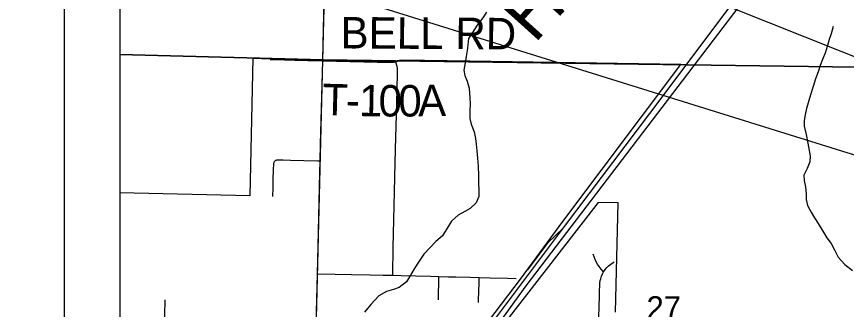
# Model space of a CAD drawing. Extents: x -38.1 to 35.9, y -2.7 to 28.5.
# Drawn here: x 18.424 to 19.92, y 16.626 to 17.155 of the extents above; entities that cross this region are included whole.
import ezdxf

# ---------------------------------------------------------------- set-up
doc = ezdxf.new("R2010")
doc.units = 0
for name, color, linetype in [('GM_X_City_Street', 7, 'Continuous'), ('GM_X_Corporation', 7, 'Continuous'), ('GM_X_Interchange_Ramps', 7, 'Continuous'), ('GM_X_Major_River_Text', 7, 'Continuous'), ('GM_X_Minor_Lake', 7, 'Continuous'), ('GM_X_Minor_River', 7, 'Continuous'), ('GM_X_Section', 7, 'Continuous'), ('GM_X_US_Location', 7, 'Continuous'), ('GM_X_US_Route', 7, 'Continuous'), ('SH_Border', 7, 'Continuous'), ('SH_Data', 7, 'Continuous')]:
    doc.layers.add(name, color=color, linetype=linetype)

msp = doc.modelspace()

# ---------------------------------------------------------------- linework, layer by layer
at = {"layer": 'GM_X_City_Street'}
for points in [[(19.1023, 16.6877), (19.1024, 16.6883), (19.1033, 16.7377), (19.1051, 16.8132), (19.1076, 16.9156), (19.1096, 16.9978), (19.1108, 17.0519), (19.1109, 17.0568), (19.1109, 17.0602), (19.1108, 17.0614), (19.1107, 17.0623), (19.1105, 17.0634), (19.1102, 17.0643), (19.1079, 17.0725), (19.1077, 17.0733)], [(18.8864, 16.8301), (18.8867, 16.8455), (18.8871, 16.8628), (18.8874, 16.8758), (18.8877, 16.8821), (18.8878, 16.8849), (18.8879, 16.8875), (18.888, 16.8889), (18.8882, 16.89), (18.8884, 16.8913), (18.8887, 16.8922), (18.889, 16.8929), (18.8897, 16.8941)], [(18.8897, 16.8941), (18.8903, 16.8946), (18.8908, 16.895), (18.8915, 16.8954), (18.8923, 16.8957), (18.8933, 16.8959), (18.8945, 16.896), (18.8989, 16.896), (18.9047, 16.896), (18.9183, 16.8957), (18.9424, 16.8951), (18.9676, 16.8945), (18.9717, 16.8944)], [(19.4824, 16.6937), (19.4782, 16.699), (19.4746, 16.7034), (19.4715, 16.708), (19.469, 16.7123), (19.4671, 16.7163), (19.4654, 16.721), (19.4638, 16.7257)], [(19.4736, 16.5934), (19.4749, 16.6502), (19.4751, 16.6582), (19.4752, 16.6622), (19.4755, 16.667), (19.4757, 16.6706), (19.476, 16.6743), (19.4766, 16.6783), (19.4773, 16.6814), (19.479, 16.6862), (19.4812, 16.6914), (19.4824, 16.6937), (19.483, 16.6948), (19.4851, 16.698), (19.4882, 16.7018), (19.4914, 16.7047), (19.4958, 16.7081), (19.4996, 16.711), (19.5018, 16.7122)], [(18.9666, 16.6904), (18.9986, 16.6898), (19.0282, 16.6892), (19.0619, 16.6885), (19.0852, 16.688), (19.1023, 16.6877), (19.1174, 16.6872), (19.1704, 16.6859), (19.1858, 16.6856), (19.2031, 16.6852), (19.2162, 16.6849), (19.2422, 16.6843), (19.2583, 16.6839), (19.278, 16.6834), (19.3092, 16.6826), (19.3247, 16.6822)], [(19.1849, 16.6433), (19.1858, 16.6849), (19.1858, 16.6856)], [(19.2571, 16.6386), (19.2573, 16.646), (19.2576, 16.6559), (19.2581, 16.677), (19.2582, 16.6831), (19.2583, 16.6839)], [(18.6838, 16.3345), (18.6838, 16.3354), (18.6842, 16.3477), (18.685, 16.3713), (18.6856, 16.3892), (18.6858, 16.3944), (18.6862, 16.3985), (18.6865, 16.4028), (18.6867, 16.4071), (18.6868, 16.4108), (18.6896, 16.5153), (18.6903, 16.5603), (18.6906, 16.5743), (18.6907, 16.5829), (18.6916, 16.616), (18.6924, 16.6435)]]:
    msp.add_lwpolyline(points, dxfattribs=at)
at = {"layer": 'GM_X_Corporation'}
for points in [[(18.6101, 15.7069), (18.8445, 16.0191), (18.9897, 16.2122), (19.0483, 16.2903), (19.2337, 16.5376), (19.4121, 16.7756), (19.566, 16.98), (19.763, 17.2432), (19.9196, 17.4482), (20.1512, 17.7579), (20.6767, 18.4541), (21.2204, 19.1713), (21.641, 19.7308)], [(18.6101, 15.3282), (18.8021, 15.6262), (18.9395, 15.8264), (19.0058, 15.9302), (19.0089, 15.9495), (19.0142, 16.0977), (19.0173, 16.1531), (19.0191, 16.1912), (19.0199, 16.2263), (19.0305, 16.2532), (19.2347, 16.519), (19.3429, 16.6685), (19.7347, 17.1834), (19.9115, 17.4163)], [(19.3461, 16.6973), (19.3827, 16.7469), (19.4098, 16.7725)]]:
    msp.add_lwpolyline(points, dxfattribs=at)
at = {"layer": 'GM_X_Interchange_Ramps'}
for points in [[(18.9764, 17.0748), (18.9782, 17.1482), (18.98, 17.2128), (18.9809, 17.2588), (18.9815, 17.283), (18.9833, 17.3477), (18.9853, 17.4235), (18.986, 17.4508), (18.9871, 17.4819), (18.9881, 17.5204), (18.9896, 17.5801)], [(18.9683, 16.7664), (18.9683, 16.7674), (18.9712, 16.8726), (18.9717, 16.8944), (18.9724, 16.9242), (18.9764, 17.0748)], [(18.9592, 16.3817), (18.9611, 16.4668), (18.9618, 16.494), (18.9638, 16.5752), (18.9639, 16.5767), (18.9656, 16.6438), (18.9666, 16.6904), (18.9683, 16.7664)]]:
    msp.add_lwpolyline(points, dxfattribs=at)
at = {"layer": 'GM_X_Major_River_Text'}
for points in [[(18.8814, 17.0773), (18.8882, 17.0771), (18.9261, 17.076), (18.9494, 17.0753), (18.9764, 17.0748)], [(18.9764, 17.0748), (19.0747, 17.0727), (19.1008, 17.0724), (19.1031, 17.0724), (19.104, 17.0725), (19.1048, 17.0727), (19.1077, 17.0733)], [(19.1077, 17.0733), (19.1108, 17.0742), (19.1136, 17.0749), (19.1159, 17.0753), (19.1175, 17.0755), (19.1189, 17.0756), (19.1208, 17.0756), (19.1239, 17.0757), (19.1507, 17.0753), (19.1794, 17.0749), (19.1957, 17.0746), (19.2123, 17.0742), (19.2302, 17.074), (19.2415, 17.0738)]]:
    msp.add_lwpolyline(points, dxfattribs=at)
at = {"layer": 'GM_X_Section'}
for points in [[(19.2717, 17.1624), (19.265, 17.1527), (19.2548, 17.1389), (19.2461, 17.1262), (19.2391, 17.1153), (19.2377, 17.1028), (19.2367, 17.0933), (19.2349, 17.0828), (19.2328, 17.0714), (19.2306, 17.0582), (19.2326, 17.0483), (19.2366, 17.0383), (19.2401, 17.0253), (19.2416, 17.0082), (19.2421, 16.9975), (19.2415, 16.9843), (19.2412, 16.971), (19.244, 16.9607), (19.2494, 16.9469), (19.2517, 16.9347), (19.253, 16.9244), (19.2543, 16.9126), (19.2555, 16.8993), (19.2563, 16.8849), (19.2571, 16.867), (19.2568, 16.853), (19.2577, 16.8423), (19.2574, 16.8298), (19.2529, 16.8185), (19.2417, 16.8081), (19.2321, 16.8026), (19.2202, 16.7961), (19.2081, 16.7854), (19.2006, 16.7726), (19.1924, 16.7591), (19.1803, 16.7488)], [(19.8964, 17.137), (19.8927, 17.1238), (19.889, 17.1133), (19.8861, 17.1023), (19.8825, 17.0903), (19.8772, 17.0771), (19.8732, 17.0662), (19.8691, 17.0549), (19.8643, 17.0425), (19.8602, 17.0282), (19.8557, 17.0135), (19.8483, 16.9886), (19.8457, 16.9772), (19.8444, 16.967), (19.8441, 16.9568), (19.8476, 16.9419), (19.8507, 16.9263), (19.8534, 16.9129), (19.8547, 16.903), (19.8541, 16.8928), (19.8496, 16.8803), (19.8437, 16.8687), (19.8442, 16.8588), (19.8466, 16.8474), (19.8479, 16.8341), (19.8476, 16.8246), (19.85, 16.8135), (19.8566, 16.8016), (19.8629, 16.7916), (19.8695, 16.7812), (19.8775, 16.7673), (19.8848, 16.7554), (19.8926, 16.7453), (19.8995, 16.7323), (19.9057, 16.7204), (19.9176, 16.7072), (19.931, 16.6962)], [(19.1803, 16.7488), (19.1586, 16.7258), (19.1487, 16.7117), (19.1423, 16.7012), (19.1271, 16.6759), (19.1139, 16.6657), (19.1035, 16.6622), (19.0909, 16.6584), (19.0774, 16.6508), (19.0628, 16.635), (19.0514, 16.6213)]]:
    msp.add_lwpolyline(points, dxfattribs=at)
at = {"layer": 'GM_X_US_Route'}
for points in [[(18.6101, 19.1036), (18.6101, 13.5671)], [(19.2642, 16.5902), (19.3329, 16.681), (19.4089, 16.7849), (19.6216, 17.068), (19.2413, 17.0743), (19.1187, 17.0762), (19.1105, 17.0748), (19.1074, 17.0738), (19.1038, 17.0731), (19.0745, 17.0733), (18.9762, 17.0754), (18.8812, 17.0778), (18.8504, 17.079), (18.8445, 16.831), (18.6101, 16.8368), (18.6101, 15.5795)], [(19.504, 16.621), (19.5086, 16.8184), (19.4726, 16.8191), (19.2369, 16.5153)]]:
    msp.add_lwpolyline(points, dxfattribs=at)
for points in [[(18.6101, 18.0958), (18.6101, 17.0862), (18.9765, 17.0768), (18.9989, 18.0871)], [(20.0086, 18.0758), (19.9831, 17.0625), (18.9765, 17.0768), (18.9989, 18.0871)], [(18.6101, 17.0862), (18.6101, 16.0783), (18.9517, 16.0707), (18.9765, 17.0768)], [(18.9765, 17.0768), (19.9831, 17.0625), (19.9577, 16.0521), (18.9517, 16.0707)]]:
    msp.add_lwpolyline(points, close=True, dxfattribs=at)
at = {"layer": 'SH_Border'}
msp.add_line((18.6101, 19.7308), (18.6101, 12.9308), dxfattribs=at)
at = {"layer": 'SH_Data'}
msp.add_line((18.5101, 19.8308), (18.5101, 12.8308), dxfattribs=at)
msp.add_lwpolyline([(18.4243, 17.3766), (21.976, 16.2689), (18.4243, 17.6847)], close=True, dxfattribs=at)

# ---------------------------------------------------------------- texts
at = {"layer": 'GM_X_Minor_Lake'}
for s, height, rotation, p in [('BELL RD', 0.05682, 359.6718, (19.0081, 17.0972)), ('T', 0.0568, 358.4698, (18.9747, 16.9769)), ('1', 0.0568, 358.9452, (19.0411, 16.9751)), ('0', 0.0568, 359.5542, (19.0767, 16.9745)), ('0', 0.0568, 0.252, (19.1125, 16.9742)), ('A', 0.0568, 0.9064, (19.1482, 16.9744)), ('-', 0.0568, 358.5818, (19.0173, 16.9757))]:
    msp.add_text(s, height=height, rotation=rotation, dxfattribs=at).set_placement(p)
at = {"layer": 'GM_X_Minor_River'}
msp.add_text('27', height=0.04186, rotation=0, dxfattribs=at).set_placement((19.5599, 16.6081))
at = {"layer": 'GM_X_US_Location'}
msp.add_text('Hardin', height=0.09468, rotation=48.0207, dxfattribs=at).set_placement((19.358, 17.1045))

doc.saveas('drawing.dxf')
